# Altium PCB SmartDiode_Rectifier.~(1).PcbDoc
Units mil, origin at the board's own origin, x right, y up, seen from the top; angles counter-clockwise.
Board outline 4217 x 3432 mil, 2 copper layers (Top Layer, Bottom Layer), stack 12.8 mil thick; 42 components, 16 nets, 86 pads, 136 vias.
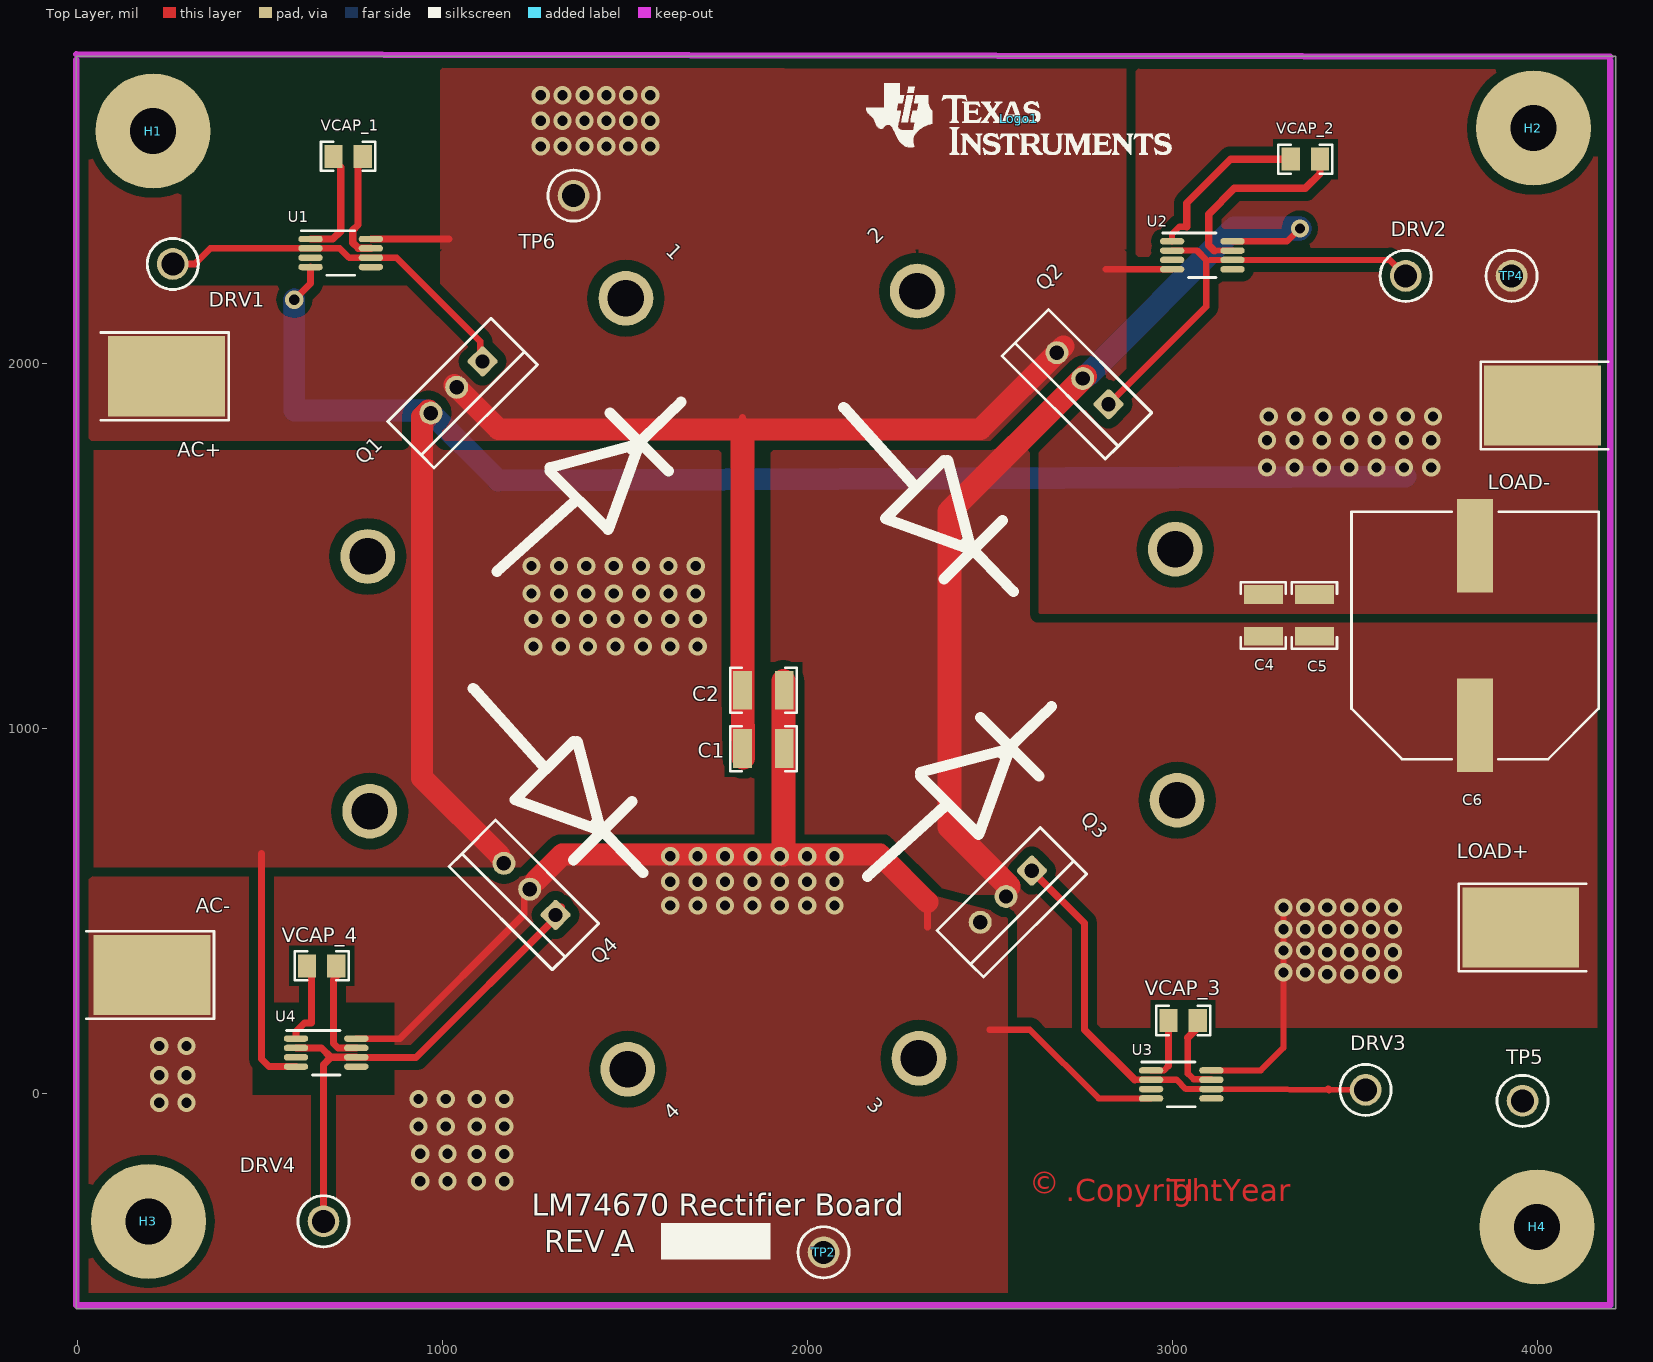
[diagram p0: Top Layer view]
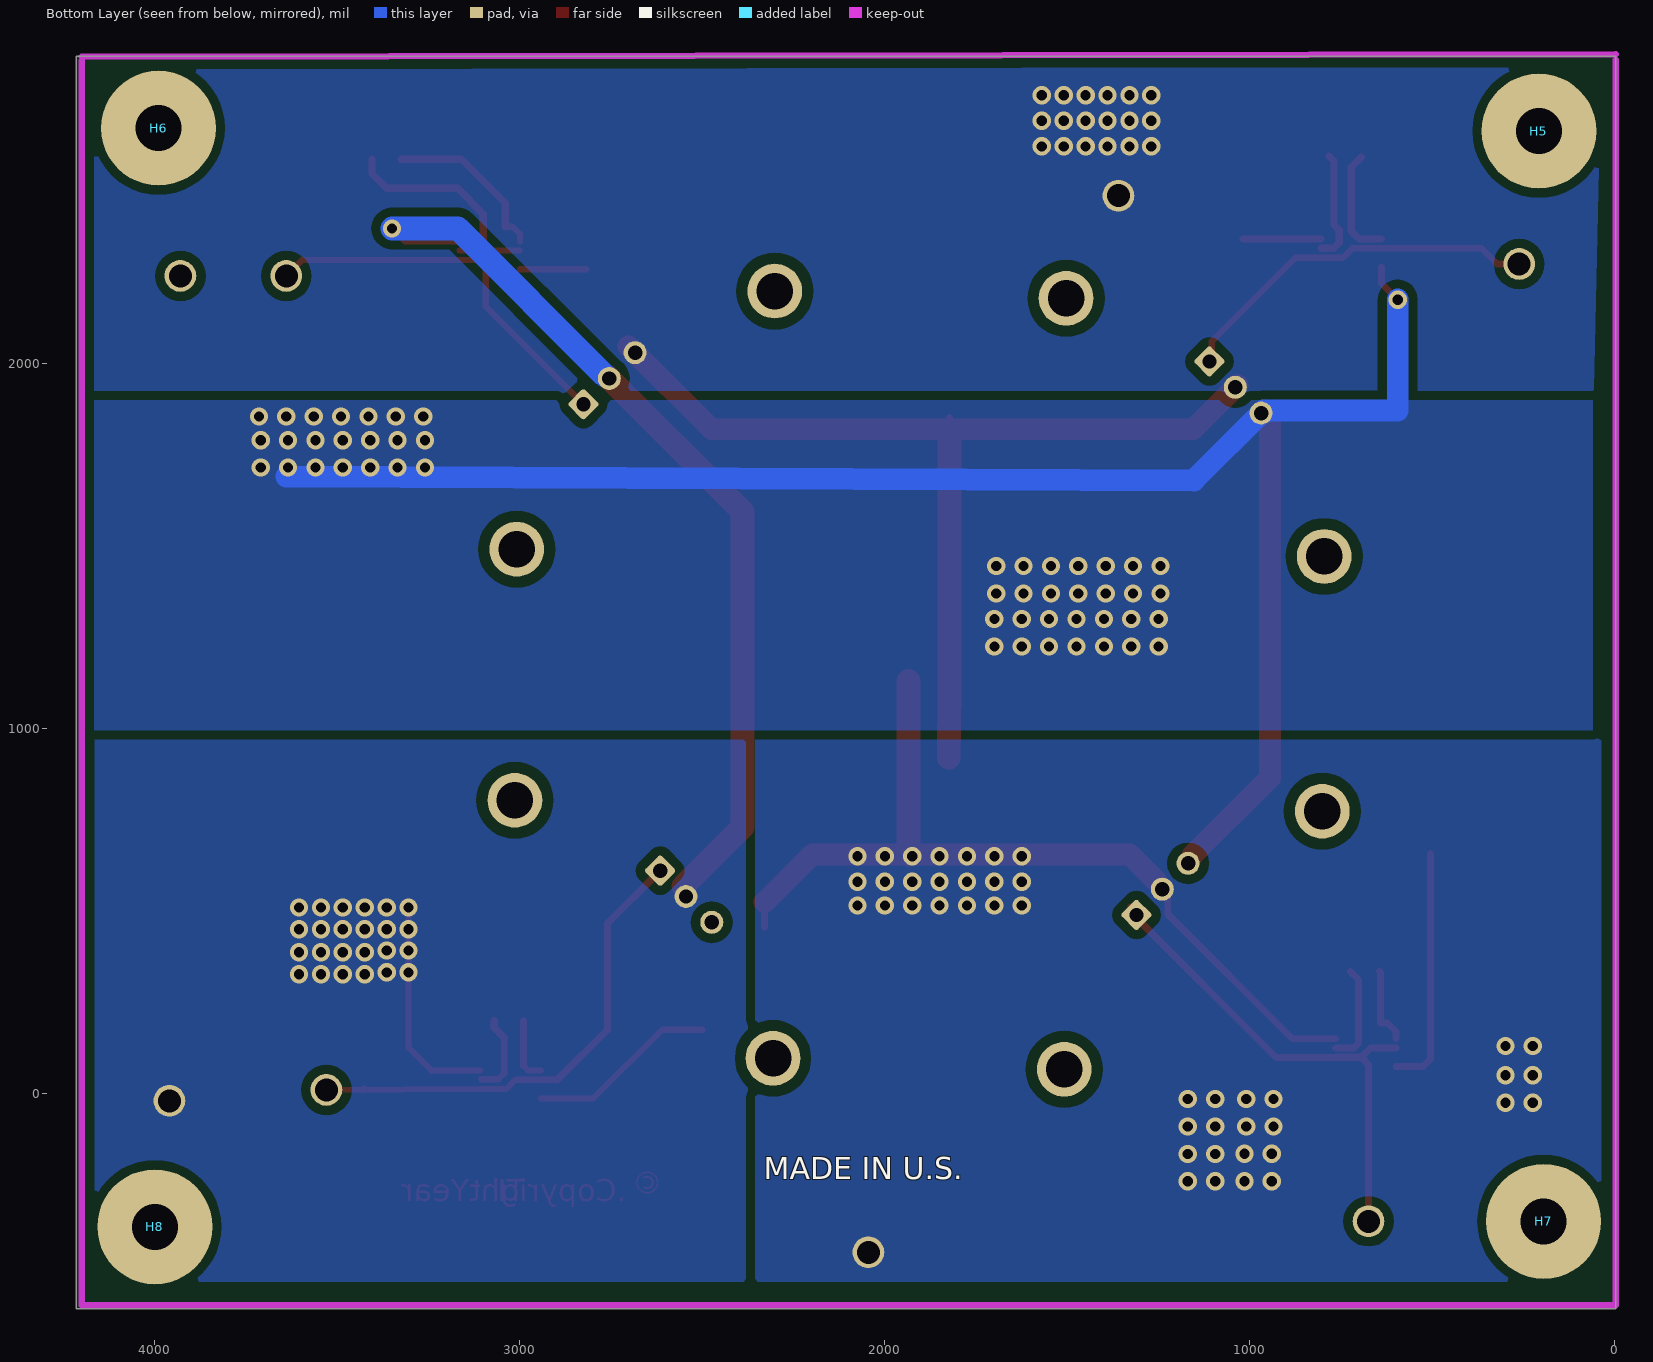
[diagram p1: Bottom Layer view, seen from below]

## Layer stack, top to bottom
Top Solder: solder mask 0.4, Solder Resist, Dk 3.5
Top Layer: signal copper 1.4
Dielectric 3: core 10, Dk 4.2
Bottom Layer: signal copper 1.4
Bottom Solder: solder mask 0.4, Solder Resist, Dk 3.5

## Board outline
-2,-590 4215,-590 4215,2842 -2,2842

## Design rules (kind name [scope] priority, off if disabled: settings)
AcuteAngle [All] p1: minimum=4.60000000000000E+0001 checktracksonly=FALSE
AssemblyTestPointUsage [All] p1: valid=2
Clearance "Clearance_HEATSINK TO POLY" [HasFootprint('HEATSINK_SK104_SERIES')] p1: gap=30
Clearance Clearance_Keepouts [((IsTrack Or IsArc) And Not InPoly) And IsFree and IsKeepOut vs ((IsTrack Or IsArc) And Not InPoly) And IsFree and IsKeepOut] p2: gap=20
Clearance Clearance_BoardEdge_MountingHoles [OnCopper and InComponentClass('Mounting Holes') vs IsKeepOut] p3: gap=28
Clearance Clearance_BoardEdge_Poly [OnCopper and InPoly vs IsKeepOut] p4: gap=25
Clearance Clearance_BoardEdge [OnCopper and Not InComponentClass('Logo') and not InComponentClass('FiducialMark') and not InRegion(1000,500,4000,800) and Not IsKeepout vs IsKeepOut] p5: gap=13
Clearance Clearance_Poly [InPolygon] p6: gap=25
Clearance Clearance_ALL [All] p7: gap=6
ComponentClearance "ComponentClearance_C6 TO C7" [InComponent('C6') vs InComponent('C7')] p1: gap=0 collisioncheckmode=3 verticalgap=0 showdistances=FALSE
ComponentClearance ComponentClearance_FETS_1 [(InComponent('FET1_A') OR  InComponent('FET1_B') OR InComponent('FET1_C')) vs (InComponent('FET1_A') OR InComponent('FET1_B') OR InComponent('FET1_C'))] p2: gap=0 collisioncheckmode=3 verticalgap=0 showdistances=FALSE
ComponentClearance ComponentClearance_FETS_2 [(InComponent('FET2_A') OR InComponent('FET2_B') OR InComponent('FET2_C')) vs (InComponent('FET2_B') OR InComponent('FET2_B') OR InComponent('FET2_C'))] p3: gap=0 collisioncheckmode=3 verticalgap=0 showdistances=FALSE
ComponentClearance ComponentClearance_MountingHoles_FiducialMarks [InComponentClass('Mounting Holes') vs InComponentClass('FiducialMark')] p4: gap=40 collisioncheckmode=3 verticalgap=10 showdistances=FALSE
ComponentClearance ComponentClearance_Shunt [InComponentClass('Header') vs InComponentClass('Shunt')] p5: gap=0 collisioncheckmode=3 verticalgap=0 showdistances=FALSE
ComponentClearance ComponentClearance_Logo [InComponentClass('Logo')] p6: gap=50 collisioncheckmode=3 verticalgap=10 showdistances=FALSE
ComponentClearance ComponentClearance_ScrewToNut [(HasFootprint('NY PMS 440 0025 PH')) vs (HasFootprint('Keystone_1902C'))] p7: gap=5 collisioncheckmode=3 verticalgap=10 showdistances=FALSE
ComponentClearance ComponentClearance_MountingHoles [InComponentClass('Mounting Holes')] p8: gap=100 collisioncheckmode=3 verticalgap=100000 showdistances=FALSE
ComponentClearance ComponentClearance_SmallPassives [HasFootprint('0201*') or HasFootprint('0402*') or HasFootprint('0508') or HasFootprint('0603*') or HasFootprint('0612') or HasFootprint('0805*') or HasFootprint('0815*') or HasFootprint('0830*') or HasFootprint('1206*') or HasFootprint('1210*') or HasFootprint('1808*') or HasFootprint('1812*') or HasFootprint('1825*') or HasFootprint('2010*') or HasFootprint('2220*') or HasFootprint('2225*') or HasFootprint('2512*') or HasFootprint('2728*') or HasFootprint('3518*') vs HasFootprint('0201*') or HasFootprint('0402*') or HasFootprint('0508') or HasFootprint('0603*') or HasFootprint('0612') or HasFootprint('0805*') or HasFootprint('0815*') or HasFootprint('0830*') or HasFootprint('1206*') or HasFootprint('1210*') or HasFootprint('1808*') or HasFootprint('1812*') or HasFootprint('1825*') or HasFootprint('2010*') or HasFootprint('2220*') or HasFootprint('2225*') or HasFootprint('2512*') or HasFootprint('2728*') or HasFootprint('3518*')] p9: gap=20 collisioncheckmode=3 verticalgap=10 showdistances=FALSE
ComponentClearance ComponentClearance_THtoSMT [IsThruComponent vs IsSMTComponent] p10: gap=50 collisioncheckmode=3 verticalgap=30 showdistances=FALSE
ComponentClearance ComponentClearance_THtoTH [IsThruComponent vs IsThruComponent] p11: gap=50 collisioncheckmode=3 verticalgap=30 showdistances=FALSE
ComponentClearance [All] p12: gap=40 collisioncheckmode=3 verticalgap=10 showdistances=FALSE
DiffPairsRouting [All] p1: maxlimit=100 minlimit=10 mostfreqgap=10 toplayer_minwidth=15 toplayer_maxwidth=15 toplayer_prefwidth=15 bottomlayer_minwidth=15 bottomlayer_maxwidth=15 bottomlayer_prefwidth=15 maxuncoupledlength=1000
FabricationTestPointUsage TestPointUsage [All] p1: valid=2 allowmultiple=FALSE
FabricationTestpoint Testpoint [All] p1: side=3 testpointundercomponent=TRUE minsize=40 maxsize=100 preferedsize=60 minholesize=0 maxholesize=40 preferedholesize=32 testpointgrid=1 allowsidetop=TRUE allowsidebottom=TRUE usegrid=TRUE gridtolerance=0.01
FanoutControl Fanout_LCC [IsLCC] p1: bgadir=Out bgaviamode=Centered fanoutstyle=Auto fanoutdirection=Alternating viagrid=1 // Fanout_LCC (Default Rule)
FanoutControl Fanout_BGA [IsBGA] p2: bgadir=Out bgaviamode=Centered fanoutstyle=Auto fanoutdirection=Alternating viagrid=1 // Fanout_BGA (Default Rule)
FanoutControl Fanout_Default [All] p4: bgadir=Out bgaviamode=Centered fanoutstyle=Auto fanoutdirection=Alternating viagrid=1 // Fanout_Default (Default Rule)
FanoutControl Fanout_Small [(CompPinCount < 5)] p5: bgadir=Out bgaviamode=Centered fanoutstyle=Auto fanoutdirection=OutThenIn viagrid=1 // Fanout_Small (Default Rule)
HoleSize [All] p1: absolutevalues=TRUE maxlimit=251 minlimit=8 maxpercent=80.000 minpercent=20.000
MinimumAnnularRing MinimumAnnularRing_ThermalPadVias [IsVia and InAnyComponent] p1: minimumring=6
MinimumAnnularRing [All] p2: minimumring=6
MinimumSolderMaskSliver MinimumSolderMaskSliver_Logo [InComponentClass('Logo') vs InComponentClass('Logo')] p1: minsoldermaskwidth=0.7
MinimumSolderMaskSliver [All] p2: minsoldermaskwidth=3.94
PlaneConnect [All] p1: planeconnectstyle=Direct reliefexpansion=10 reliefentries=4 reliefconductorwidth=10 reliefairgap=10
PolygonConnect [All] p1: connectstyle=Direct reliefconductorwidth=10 reliefentries=4 polygonreliefangle="90 Angle" airgapwidth=10
RoutingVias ThermalPadVias [IsVia and InAnyComponent] p1: holewidth=8 width=28 viastyle="Through Hole" minholewidth=8 minwidth=28 maxholewidth=12.99 maxwidth=40
RoutingVias [All] p2: holewidth=16 width=34 viastyle="Through Hole" minholewidth=8 minwidth=28 maxholewidth=40 maxwidth=65
SilkToBoardRegionClearance [Not ((IsComment or IsDesignator) And (Hide <> 'False')) and not InRegion(1000,500,4000,800)] p1:
SilkToSilkClearance SilkToSilkClearance_Pb-FreeLogo [(HasFootprint('Pb-Free_Overlay_Medium') OR HasFootprint('Pb-Free_Overlay_Small')) vs (HasFootprint('Pb-Free_Overlay_Medium') OR HasFootprint('Pb-Free_Overlay_Small'))] p1: silktosilkclearance=0
SilkToSilkClearance [All] p2: silktosilkclearance=5
SilkToSolderMaskClearance "Silk to Solder Mask Opening" [All] p1: minsilkscreentomaskgap=1 clearancetoexposedcopper=FALSE
SolderMaskExpansion [All] p1: expansion=1.97
UnpouredPolygon [All] p1: allowunpoured=FALSE
Width [All] p1: maxlimit=100 minlimit=6 preferedwidth=10 checkconnectedcopper=TRUE
14 further rules are at their usual default settings.

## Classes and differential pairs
component class "Mounting Holes": H1 H2 H3 H4
component class Logo: Logo1
component class rectifier_Hardware: H1 H2 H3 H4 H5 H6 H7 H8 Logo1
component class SmartDiodeRectifier: 1 2 3 4 AC+ AC- C1 C2 C4 C5 C6 DRV1 DRV2 DRV3 DRV4 FET2 LOAD+ LOAD- Q1 Q2 Q3 Q4 TP2 TP4 TP5 TP6 U1 U2 U3 U4 VCAP VCAP_1 VCAP_2 VCAP_3 VCAP_4

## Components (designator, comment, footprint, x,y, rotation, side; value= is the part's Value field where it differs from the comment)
1 "HEATSINK_SK_104_SERIES" HEATSINK_SK104_SERIES 1150,1825 r45 top
2 "HEATSINK_SK_104_SERIES" HEATSINK_SK104_SERIES 2655,1845 r135 top
3 "HEATSINK_SK_104_SERIES" HEATSINK_SK104_SERIES 2660,450 r225 top
4 "HEATSINK_SK_104_SERIES" HEATSINK_SK104_SERIES 1155,420 r135 top
AC+ "6091" 6091 60,1965 r0 top
AC- "6092" 6092 20,325 r0 top
C1 "GRM32ER71H475KA88L" 1210 1880,945 r180 top
C2 "GRM32ER71H475KA88L" 1210 1880,1105 r180 top
C4 "GRM32ER71H475KA88L" 1210 3250,1310 r270 top
C5 "GRM32ER71H475KA88L" 1210 3390,1310 r270 top
C6 "EEV-FK1H102M" SM_RADIAL_J16 3830,1255 r90 top
DRV1 "5014" Keystone5014 262.2,2272.8 r270 top
DRV2 "5014" Keystone5014 3640,2240 r90 top
DRV3 "5014" Keystone5014 3530,10 r90 top
DRV4 "5014" Keystone5014 675,-350 r0 top
H1 "NY PMS 440 0025 PH" "NY PMS 440 0025 PH" 208,2637 r0 top locked
H2 "NY PMS 440 0025 PH" "NY PMS 440 0025 PH" 3990,2645 r0 top locked
H3 "NY PMS 440 0025 PH" "NY PMS 440 0025 PH" 195,-350 r0 top locked
H4 "NY PMS 440 0025 PH" "NY PMS 440 0025 PH" 4000,-365 r0 top locked
H5 "1902C" Keystone_1902C 208,2637 r180 bottom locked
H6 "1902C" Keystone_1902C 3990,2645 r180 bottom locked
H7 "1902C" Keystone_1902C 195,-350 r180 bottom locked
H8 "1902C" Keystone_1902C 4000,-365 r180 bottom locked
LOAD+ "6091" 6091 4140,455 r180 top
LOAD- "6092" 6092 4200,1885 r180 top
Logo1 "Texas Instruments" TI_Stacked_Overlay_Small 2580,2670 r0 top
Q1 "CSD18532KCS" KCS0003A 1040,1935 r315 top
Q2 "CSD18532KCS" KCS0003A 2755,1959.14 r225 top
Q3 "CSD18532KCS" KCS0003A 2545,540 r315 top
Q4 "CSD18532KCS" KCS0003A 1240,560 r225 top
TP2 "5011" Keystone5011 2045,-435 r0 top
TP4 "5011" Keystone5011 3930,2240 r0 top
TP5 "5010" Keystone5010 3960,-20 r0 top
TP6 "5010" Keystone5010 1360,2460 r0 top
U1 "LM74670QDGKRQ1" DGK0008A_N 722.2,2302.8 r0 top
U2 "LM74670QDGKRQ1" DGK0008A_N 3082.68,2296.61 r0 top
U3 "LM74670QDGKRQ1" DGK0008A_N 3025,25 r0 top
U4 "LM74670QDGKRQ1" DGK0008A_N 682.32,112.2 r0 top
VCAP_1 "08053D474KAT2A" 0805_HV 742.2,2567.8 r180 top
VCAP_2 "08053D474KAT2A" 0805_HV 3365,2560 r180 top
VCAP_3 "08053D474KAT2A" 0805_HV 3030,200 r180 top
VCAP_4 "08053D474KAT2A" 0805_HV 670,350 r180 top

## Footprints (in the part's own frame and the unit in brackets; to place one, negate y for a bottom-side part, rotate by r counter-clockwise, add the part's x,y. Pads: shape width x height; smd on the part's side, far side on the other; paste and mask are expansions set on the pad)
0805_HV [mil] "0805 with 30mil clearance between pads"
  rect 50x63 smd: 1(-40,0) 2(40,0)
  silkscreen extent -74,-40 74,40, body extent -43,-29 43,29, height 43
1210 [mm] "1210 from SM-752 data"
  rect 1.3x2.7 smd: 1(-1.45,0) 2(1.45,0)
  silkscreen extent -2.32,-1.57 2.32,1.57, body extent -1.7,-1.35 1.7,1.35, height 1.35
6091 [mil] "Keystone Insulated End Launch Banana Jack"
  rect 320x220 smd: 1(185,0)
  silkscreen extent 5,-120 355,120, body extent -666,-216 271,216, height 227
6092 [mil] "Keystone Insulated End Launch Banana Jack"
  rect 320x220 smd: 1(185,0)
  silkscreen extent 5,-120 355,120, body extent -666,-216 271,216, height 227
DGK0008A_N [mm] "TSOP, 8-Leads, Body 3x3mm, Pitch 0.65mm, IPC Medium Density"
  oval 1.7x0.45 smd: 1(-2.1,0.975) 2(-2.1,0.325) 3(-2.1,-0.325) 4(-2.1,-0.975) 5(2.1,-0.975) 6(2.1,-0.325) 7(2.1,0.325) 8(2.1,0.975)
  silkscreen extent -2.75,-1.55 0.95,1.55, body extent -2.45,-1.5 2.45,1.5, height 0.94
HEATSINK_SK104_SERIES [mil]
  round 150 hole 100: 1(-500,0) 2(500,0)
KCS0003A [mm] "Flange Mount, 3-Leads, Body 10.16x4.51mm, Pitch 2.54mm"
  rrect25% 1.6x1.6 hole 1: 1(0,2.54)
  round 1.6 hole 1: 2(0,0) 3(0,-2.54)
  silkscreen extent -1.71,-5.08 2.86,5.08, body extent -1.71,-5.09 2.86,5.08, height 18.63
Keystone5010 [mil] "Keystone Multipurpose loops"
  round 87 hole 63: 1(0,0)
  silkscreen extent -70,-70 70,70, body extent -63,-63 63,62, height 319
Keystone5011 [mil] "Keystone Multipurpose loops"
  round 87 hole 63: 1(0,0)
  silkscreen extent -70,-70 70,70, body extent -63,-63 63,62, height 319
Keystone5014 [mil] "Keystone Multipurpose loops"
  round 87 hole 63: 1(0,0)
  silkscreen extent -70,-70 70,70, body extent -63,-63 63,62, height 319
Keystone_1902C [mil] "Hex Standoff, 4-40 threaded, nylon"
  body extent -145,-126 146,126, height 501
"NY PMS 440 0025 PH" [mm] "4-40 nylon screw and mounting hole"
  round 8 hole 3.2: 1(0,0)
  body extent -3.3,-3.3 3.3,3.3, height 2.69
SM_RADIAL_J16 [mm] "16 x 16.5mm:  Panasonic J16"
  rect 6.5x2.5 smd: 1(-6.25,0) 2(6.25,0)
  silkscreen extent -8.6,-8.6 8.6,8.6, body extent -8.6,-8.6 8.6,8.6, height 17
TI_Stacked_Overlay_Small [mil]
  silkscreen extent -418,-98 418,98

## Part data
1 2 3 4: "Heatsink,  Vertical-mount TO-220"
AC+ LOAD+: "Standard Banana Jack, Insulated, Red"
AC- LOAD-: "Standard Banana Jack, Insulated, Black"
C1 C2 C4 C5: "CAP, CERM, 4.7 µF, 50 V, +/- 10%, X7R, 1210"
C6: "CAP, AL, 1000 µF, 50 V, +/- 20%, 0.073 ohm, SMD"
DRV1 DRV2 DRV3 DRV4: "Test Point, Multipurpose, Yellow, TH"
H1 H2 H3 H4: "Machine Screw, Round, #4-40 x 1/4, Nylon, Philips panhead"
H5 H6 H7 H8: "Standoff, Hex, 0.5\"L #4-40 Nylon"
Logo1: library part TI_Logo, "Texas Instrument Corporate Signature"
Q1 Q2 Q3 Q4: "MOSFET, N-CH, 60 V, 100 A, KCS0003A"
TP2 TP4: "Test Point, Multipurpose, Black, TH"
TP5 TP6: "Test Point, Multipurpose, Red, TH"
U1 U2 U3 U4: "Reverse Polarity Protection Smart Diode Rectifier Controller, DGK0008A"
VCAP_1 VCAP_2 VCAP_3 VCAP_4: "CAP, CERM, 0.47 µF, 25 V, +/- 10%, X5R, 0805"

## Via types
v1: diameter 50, hole 28, Top Layer to Bottom Layer, 136 vias

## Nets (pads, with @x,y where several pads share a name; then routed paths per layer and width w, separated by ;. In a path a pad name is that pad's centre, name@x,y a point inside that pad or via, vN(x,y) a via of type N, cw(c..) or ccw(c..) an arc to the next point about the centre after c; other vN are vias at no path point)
DRIVE_1: DRV1.1 Q1.1 U1.2 U1.6 | length 1013.6
  Top Layer w18: DRV1.1 322.2,2272.8 365,2315.59 U1.2 719.41,2315.59 745,2290 U1.6 875,2290 1104.04,2060.96 Q1.1@1104.04,2012.38
DRIVE_2: DRV2.1 Q2.1 U2.2 U2.6 | length 1156.1
  Top Layer w17: U2.2 3067.88,2309.41 ; 3103.82,2283.82 U2.6 3596.18,2283.82
  Top Layer w18: Q2.1@2831.78,1894.5 3093.47,2156.19 3093.47,2283.82 3067.88,2309.41 ; 3596.18,2283.82 DRV2.1
DRIVE_3: DRV3.1 Q3.1 U3.2 U3.6 | length 1358.5
  Top Layer w17: 2897.2,37.8 U3.2 3012.2,37.8 3037.8,12.2 U3.6 DRV3.1
  Top Layer w20: Q3.1@2622.52,635.97 2622.52,603.9 2760,466.42 2760,175 2897.2,37.8 ; 3427.8,12.2 3430,10
DRIVE_4: DRV4.1 Q4.1 U4.2 U4.6 | length 1374.8
  Top Layer w20: U4.2 669.53,125 695.12,99.41 ; DRV4.1 675,79.29 695.12,99.41 ; Q4.1@1326.58,511.01 1326.58,496.58 928.68,98.68 765.73,98.68 U4.6 695.12,99.41
NetAC+_1: AC+.1 C1.2 C2.2 Q1.2 Q2.3 TP6.1 U1.8 U2.4 | length 3141.4
  Top Layer w17: 2818.23,2258.23 U2.4
  Top Layer w19: U1.8 1018.82,2341.18 ; 1822.91,1820 1822.91,1852.09
  Top Layer w60: Q1.2@1033.33,1941.67 1155,1820 1822.91,1820 2474.73,1820 Q2.3@2702.51,2047.35
  Top Layer w65: 1822.91,1820 C2.2 C1.2@1825,920
  other v1: 1270,2595 1330,2595 1390,2595 1450,2595 1510,2595 1570,2595 1270,2665 1330,2665 1390,2665 1450,2665 1510,2665 1570,2665 1270,2735 1330,2735 1390,2735 1450,2735 1510,2735 1570,2735
NetAC-_1: AC-.1 C1.1 C2.1 Q3.3 Q4.2 TP2.1 U3.4 U4.8 | length 2929.2
  Top Layer w17: 2500,175 2610,175 2798.39,-13.39 U3.4
  Top Layer w18: U4.8 884.41,150.59
  Top Layer w19: 884.41,150.59 1225,491.18 1225,550.86 Q4.2@1255.87,581.72 ; 2329.29,455.71 2329.29,524.29
  Top Layer w60: Q4.2@1255.87,581.72 1329.14,655 1935,655 2198.58,655 2329.29,524.29 ; C2.1@1935,1102.91 C2.1
  Top Layer w65: v1@1935,655 C2.1@1935,1130
  other v1: 940,-240 1015,-240 1095,-240.43 1170,-240.43 940,-165 1015,-165 1095,-165.43 1170,-165.43 935,-90 1010,-90 1095,-90 1170,-90 225,-25 300,-25 935,-15 1010,-15 1095,-15 1170,-15 225,50 300,50 225,130 300,130 1625,515 1700,515 1775,515 1850,515 1925,515 2000,515 2075,515 1625,580 1700,580 1775,580 1850,580 1925,580 2000,580 2075,580 1625,650 1700,650 1775,650 1850,650 1925,650 2000,650 2075,650
NetC4_1: C4.1 C5.1 C6.2 LOAD-.1 Q1.3 Q4.3 TP4.1 U1.4 U4.4 | length 5523.5
  Top Layer w19: 505,658.14 505,95 526.18,73.82 U4.4
  Top Layer w20: v1@590,2170 639.53,2219.53 U1.4
  Top Layer w60: Q1.3@962.62,1870.96 945,1853.35 945,865 Q4.3@1157.57,652.43
  Bottom Layer w60: v1(595,2175) 595,1870.96 962.62,1870.96 1153.58,1680 3640,1690
  other v1: 1250,1225 1325,1225 1400,1225 1475,1225 1550,1225 1625,1225 1700,1225 1250,1300 1325,1300 1400,1300 1475,1300 1550,1300 1625,1300 1700,1300 1245,1370 1320,1370 1395,1370 1470,1370 1545,1370 1620,1370 1695,1370 1245,1445 1320,1445 1395,1445 1470,1445 1545,1445 1620,1445 1695,1445 3260,1715 3335,1715 3410,1715 3485,1715 3560,1715 3635,1715 3710,1715 3260,1790 3335,1790 3410,1790 3485,1790 3560,1790 3635,1790 3710,1790 3265,1855 3340,1855 3415,1855 3490,1855 3565,1855 3640,1855 3715,1855
NetC4_2: C4.2 C5.2 C6.1 LOAD+.1 Q2.2 Q3.2 TP5.1 U2.8 U3.8 | length 3151.6
  Top Layer w17: U3.8 3243.39,63.39 3305,125 3305,485 ; U2.8 3315,2335 v1(3350,2370)
  Top Layer w60: Q3.2@2551.81,565.26 Q3.2@2551.81,568.19
  Top Layer w65: Q3.2@2551.81,568.19 2390,730 2390,1280 2390,1594.14 Q2.2@2761.07,1965.21
  Bottom Layer w65: Q2.2@2767.69,1967.69 3170,2370 v1(3350,2370)
  other v1: 3425,327 3485,327 3545,327 3605,327 3305,332 3365,332 3425,387 3485,387 3545,387 3605,387 3305,392 3365,392 3305,450 3365,450 3425,450 3485,450 3545,450 3605,450 3305,510 3365,510 3425,510 3485,510 3545,510 3605,510
NetU1_1: U1.1 VCAP_1.2 | length 302
  Top Layer w20: U1.1 700.59,2341.18 722.2,2362.8 VCAP_1.2@722.2,2537.8 ; VCAP_1.2@695,2565 VCAP_1.2@720,2540
NetU1_7: U1.7 VCAP_1.1 | length 304.6
  Top Layer w20: VCAP_1.1 769.41,2555 769.41,2379.46 755.42,2365.47 755.42,2330.88 769.41,2316.89 769.41,2315.59 U1.7
NetU2_1: U2.1 VCAP_2.2 | length 468
  Top Layer w17: U2.1 3000,2355 3020,2375 3040,2375
  Top Layer w20: 3040,2375 3040,2440 3160,2560 VCAP_2.2
NetU2_7: U2.7 VCAP_2.1 | length 547.4
  Top Layer w17: 3115,2309.41 U2.7
  Top Layer w20: 3115,2309.41 3100,2324.41 3100,2409.41 3170.59,2480 3365,2480 3405,2520 VCAP_2.1
NetU3_1: U3.1 VCAP_3.2 | length 177.1
  Top Layer w17: U3.1 2977.8,63.39 2990,75.59
  Top Layer w20: 2990,75.59 VCAP_3.2
NetU3_7: U3.7 VCAP_3.1 | length 226.6
  Top Layer w17: 3042.74,55 3058.71,39.03 U3.7@3106.44,39.03
  Top Layer w19: 3042.74,55 3042.74,152.74
  Top Layer w20: 3042.74,152.74 3070,180 VCAP_3.1
NetU4_1: U4.1 VCAP_4.2 | length 214.4
  Top Layer w19: U4.1 599.65,169.65 623.27,193.27 642.32,193.27 642.32,332.32 VCAP_4.2@645,335
NetU4_7: U4.7 VCAP_4.1 | length 275
  Top Layer w19: VCAP_4.1@725,335 702.26,312.26 702.26,137.26 714.53,125 U4.7
pads on no net: 1.1 1.2 2.1 2.2 3.1 3.2 4.1 4.2 H1.1 H2.1 H3.1 H4.1 U1.3 U1.5 U2.3 U2.5 U3.3 U3.5 U4.3 U4.5

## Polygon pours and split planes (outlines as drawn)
NetC4_1 on Top Layer "Top Layer-NetC4_1" (solid, remove dead copper, pour order 11): 2635,2830 4185,2830 4185,1315 2635,1315
NetC4_2 on Top Layer "Top Layer-NetC4_2" (solid, pour order 16): 1900,1765 4165,1765 4165,180 3395,180 2555,180 2555,545 1900,545
NetC4_1 on Top Layer "Top Layer-NetC4_1" (solid, remove dead copper, pour order 12): 45,1905 1855,1905 1855,620 45,620
NetAC+_1 on Top Layer "Top Layer-NetAC+_1" (solid, remove dead copper, pour order 10): 29.98,2313.54 29.98,1788.54 2414.98,1788.54 2874.98,1788.54 2874.98,2213.54 2874.98,2313.54 1574.98,2313.54 995,2313.53 995,2213.54 284.98,2213.54 284.98,2813.54 994.98,2813.54 994.98,2313.54 2874.98,2313.54 2874.98,2838.54 694.98,2838.54 29.98,2838.54
NetAC-_1 on Top Layer "Top Layer-NetAC-_1" (solid, remove dead copper, pour order 13): 5,600 1215,600 1230,600 1315,685 2205,685 2210,685 2355,540 2550,490 2550,345 2550,-590 -2,-590
NetC4_2 on Bottom Layer "Bottom Layer-NetC4_2" (solid, remove dead copper, pour order 20): 2362.45,975 4165,975 4165,-515 2367.52,-515
NetAC-_1 on Bottom Layer "Bottom Layer-NetAC-_1" (solid, remove dead copper, pour order 19): 37.81,985 37.81,-515 2355,-515 2355,985
NetAC+_1 on Bottom Layer "Bottom Layer-NetAC+_1" (solid, remove dead copper, pour order 18): 39.03,2810 4170,2810 4170,1915 57.55,1915
NetC4_1 on Bottom Layer "Bottom Layer-NetC4_1" (solid, remove dead copper, pour order 17): 60,1900 60,995 4195,995 4195,1900

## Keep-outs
Keep-Out Layer:
  lines w18: -2,2831.88 -2,-580 4200,-580 4200,2830 ; -2,2847 4200,2840
  text ".Layer_Name" at -2109,-1674.49 h60

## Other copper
Top Layer:
  pour cut-out: 480,250 870,250 870,-5 480,-5
  text "©" at 2609,-295 h105
  text ".CopyrightYear" at 2709,-295 h60
  text "TI" at 2985,-295 h60
  text ".Layer_Name" at -2109,-1674.49 h60
Bottom Layer:
  text ".Layer_Name" at -2109,-1674.49 h60

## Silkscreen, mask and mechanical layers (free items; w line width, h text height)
Top Overlay:
  region: 1900,-355 1600,-355 1600,-455 1900,-455
  lines w30: 1085,1110 1275,900 ; 1150,1430 1360,1620 ; 1295,1705 1455,1545 1540,1780 1295,1715 ; 1360,640 1520,800 ; 1360,965 1200,805 1435,720 1370,965 ; 1420,740 1550,605 ; 1460,1865 1620,1705 ; 1520,1765 1655,1895 ; 2100,1880 2290,1670 ; 2165,595 2375,785 ; 2310,870 2470,710 2555,945 2310,880 ; 2375,1410 2535,1570 ; 2375,1735 2215,1575 2450,1490 2385,1735 ; 2435,1510 2565,1375 ; 2475,1030 2635,870 ; 2535,930 2670,1060
  text "LM74670 Rectifier Board" at 1245,-335 h60
  text "REV A" at 1280,-435 h60
  text "-" at 1460,-465 h60
  text ".Layer_Name" at -2109,-1674.49 h60
Bottom Overlay:
  text "MADE IN U.S." at 2331.81,-234.74 h60
  text ".Layer_Name" at -2109,-1674.49 h60
Top Paste:
  text ".Layer_Name" at -2109,-1674.49 h60
Bottom Paste:
  text ".Layer_Name" at -2109,-1674.49 h60
Top Solder:
  text ".Layer_Name" at -2109,-1674.49 h60
  text ".Layer_Name" at -2109,-1674.49 h60
Bottom Solder:
  text ".Layer_Name" at -2109,-1674.49 h60
Drill Guide:
  text ".Layer_Name" at -2109,-1674.49 h60
M1 Board Outline:
  lines w10: -2,-580 -2,2840 4195,2840 4195,-580 -2,-580
  text ".Layer_Name" at -2109,-1674.49 h60
M2 Board Dimensions:
  rectangle: -2686,-1091 -2561,-966
  rectangle: -2561,-1216 -2186,-1091
  lines w7: -2686,-1091 -1686,-1091 ; -2686,-966 -2686,-1216 -1686,-1216 -1686,-966 ; -2686,-963 -1686,-963 ; -2561,-1216 -2561,-966 ; -2436,-1216 -2436,-966 ; -2186,-1216 -2186,-966 ; -1936,-1216 -1936,-966
  text ".Layer_Name" at -2109,-1674.49 h60
M3 3D STEP Top:
  text ".Layer_Name" at -2109,-1674.49 h60
M4 3D STEP Bottom:
  text ".Layer_Name" at -2109,-1674.49 h60
M5 Assembly Top:
  lines w10: -2978,-1746.17 3622,-1746.17 ; -2978,-1542.83 3624,-1542.83 ; -2978,-1339.5 -2978,-1949.5 1027,-1949.5 3624,-1949.5 3624,-1339.5 -2977.5,-1339.5 -2977.5,-1949.5 -1402,-1949.5 ; -513,-1949.5 -513,-1339.5 ; 754,-1542.83 754,-1339.5 ; 1594,-1542.83 1594,-1339.5 ; 2216,-1956 2216,-1753.17
  text "PCB VIEWED FROM TOP SIDE" at -2914.5,-1471.67 h60
  text "BOARD #:" at -438,-1471.67 h60
  text ".PRJ_Number" at 107.5,-1471.67 h60
  text "REV:" at 952,-1471.67 h60
  text ".PCB_Rev" at 1243.5,-1471.67 h60
  text "SVN REV:" at 1790,-1471.67 h60
  text ".VersionControl_RevNumber" at 2296,-1471.67 h60
  text "PLOT NAME =" at -2914.5,-1880.34 h60
  text ".plot_File_Name" at -2109,-1880.34 h60
  text "GENERATED    :" at -436,-1880.34 h60
  text ".Print_Date" at 433.5,-1880.34 h60
  text ".Print_Time" at 1162.5,-1880.34 h60
  text "TEXAS INSTRUMENTS" at 2427,-1880.34 h60
M6 Assembly Bottom:
  lines w10: -2978.5,-1543.33 3623.5,-1543.33 ; -2976.5,-1746.67 3623.5,-1746.67 ; -1570.5,-1956.5 -1570.5,-1753.67 ; -948.5,-1543.33 -948.5,-1340 ; -108.5,-1543.33 -108.5,-1340 ; 1158.5,-1950 1158.5,-1340 ; 2047.5,-1950 3623,-1950 3623,-1340 -2978.5,-1340 -2978.5,-1950 -381.5,-1950 3623.5,-1950 3623.5,-1340
  text "PCB VIEWED FROM BOTTOM SIDE" at 3280,-1290 h60
  text ".VersionControl_RevNumber" at -1650.5,-1472.17 h60
  text "SVN REV:" at -1144.5,-1472.17 h60
  text ".PCB_Rev" at -598,-1472.17 h60
  text "REV:" at -306.5,-1472.17 h60
  text ".PRJ_Number" at 538,-1472.17 h60
  text "BOARD #:" at 1083.5,-1472.17 h60
  text "TEXAS INSTRUMENTS" at -1781.5,-1880.84 h60
  text ".Print_Time" at -517,-1880.84 h60
  text ".Print_Date" at 212,-1880.84 h60
  text "GENERATED    :" at 1081.5,-1880.84 h60
  text ".plot_File_Name" at 2754.5,-1880.84 h60
  text "PLOT NAME =" at 3560,-1880.84 h60
M9 Title Sheet:
  drawing of 57 lines, arcs and shapes, not listed
  text "1" at -1946.16,7220.5 h70
  text "2" at 549.5,7220.5 h70
  text "3" at 3038.84,7220.5 h70
  text "4" at 5545.51,7220.5 h70
  text "5" at 8044.5,7220.5 h70
  text "6" at 10549.5,7220.5 h70
  text "A" at -3102.5,6077.5 h70
  text "A" at 11697.5,6077.5 h70
  text "B" at -3102.5,3697.5 h70
  text "B" at 11697.5,3697.5 h70
  text "C" at -3102.5,1322.5 h70
  text "C" at 11697.5,1322.5 h70
  text "PROJECT TITLE:" at 8657.5,-538.5 h45
  text "DESIGNED FOR:" at 8657.5,-839.5 h45
  text ".PRJ_Customer" at 8707.5,-979.5 h70
  text "D" at -3102.5,-1047.5 h70
  text "D" at 11697.5,-1047.5 h70
  text "FILE NAME:" at 8657.5,-1139.5 h45
  text ".PCB_File_Name_No_Path" at 8707.5,-1259.5 h70
  text "Texas Instruments (TI) and/or its licensors do not warrant the accuracy or completeness of this specification" at 3688,-1421.34 h45
  text "ENGINEER:" at 8657.5,-1429.5 h45
  text "LAYOUT BY:" at 10162.5,-1429.5 h45
  text "or any information contained therein. TI and/or its licensors do not warrant that this design will meet" at 3643.01,-1534 h45
  text ".PRJ_Engineer" at 8707.5,-1584.49 h70
  text ".PCB_Layout" at 10213,-1584.49 h70
  text "the specifications, will be suitable for your application or fit for any particular purpose, or will operate in" at 3643.01,-1646.67 h45
  text ".Layer_Name" at -2109,-1674.49 h60
  text "ALTIUM DESIGNER VERSION:" at 10162.5,-1739.5 h45
  text "an implementation. TI and/or its licensors do not warrant that the design is production worthy. You should" at 3643.01,-1759.33 h45
  text "completely validate and test your design implementation to confirm the system functionality for your application." at 3688,-1872 h45
  text ".print_Scale" at 8707.5,-1872.83 h70
  text ".Application_BuildNumber" at 10213,-1872.83 h70
  text "1" at -1946.16,-2079.5 h70
  text "2" at 549.5,-2079.5 h70
  text "3" at 3038.84,-2079.5 h70
  text "4" at 5545.51,-2079.5 h70
  text "5" at 8044.5,-2079.5 h70
  text "6" at 10549.5,-2079.5 h70
M11 Gerber Information:
  lines w10: -2978,-1746.17 3622,-1746.17 ; -2978,-1542.83 3624,-1542.83 ; -2978,-1339.5 -2978,-1949.5 1027,-1949.5 3624,-1949.5 3624,-1339.5 -2977.5,-1339.5 -2977.5,-1949.5 -1402,-1949.5 ; -513,-1949.5 -513,-1339.5 ; 754,-1542.83 754,-1339.5 ; 1594,-1542.83 1594,-1339.5 ; 2216,-1956 2216,-1753.17
  text ".PCB_Rev" at 1370,-1470 h60
  text "ALL ARTWORK VIEWED FROM TOP SIDE" at -2914.5,-1471.67 h60
  text "BOARD #:" at -438,-1471.67 h60
  text ".PRJ_Number" at 107.5,-1471.67 h60
  text "REV:" at 952,-1471.67 h60
  text "SVN REV:" at 1790,-1471.67 h60
  text ".VersionControl_RevNumber" at 2296,-1471.67 h60
  text "LAYER NAME =" at -2914.5,-1674.49 h60
  text "PLOT NAME =" at -2914.5,-1880.34 h60
  text ".plot_File_Name" at -2109,-1880.34 h60
  text "GENERATED    :" at -436,-1880.34 h60
  text ".Print_Date" at 433.5,-1880.34 h60
  text ".Print_Time" at 1162.5,-1880.34 h60
  text "TEXAS INSTRUMENTS" at 2427,-1880.34 h60
M12 Stackup:
  text ".Layer_Name" at -2109,-1674.49 h60
M13 Component Bodies Top:
  text ".Layer_Name" at -2109,-1674.49 h60
M15 Courtyards Top:
  text ".Layer_Name" at -2109,-1674.49 h60
Drill Drawing:
  text ".Layer_Name" at -2109,-1674.49 h60

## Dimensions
-2,2842 to -2,-590 on M2 Board Dimensions
-2,-590 to 4215,-590 on M2 Board Dimensions
-2686,-1216 to -1686,-1216 on M2 Board Dimensions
